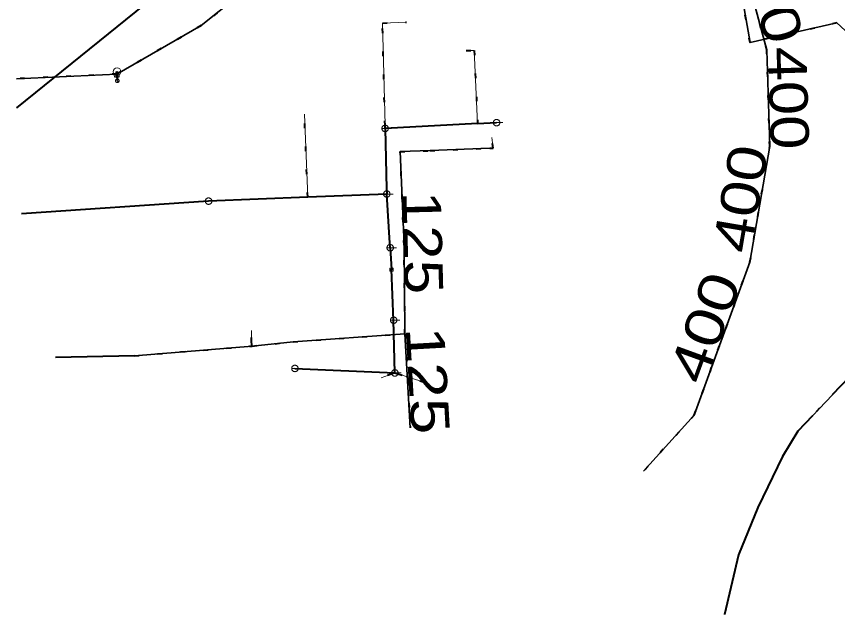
# Model space of a CAD drawing. Extents: x -968691 to -140888, y -1376050 to -879856.
# Drawn here: x -648096 to -647839.9, y -1059378.8 to -1059192.1 of the extents above; entities that cross this region are included whole.
import ezdxf
from ezdxf.enums import TextEntityAlignment as Align

# ---------------------------------------------------------------- set-up
doc = ezdxf.new("R2010")
doc.units = 0
doc.header["$LTSCALE"] = 4.8
doc.header["$PDMODE"] = 32
doc.header["$PDSIZE"] = 2.4
for name, pattern in [('DASH_DOUBLE_DOT', [9.2, 5, -1.2, 0.3, -1.2, 0.3, -1.2]), ('DOTTED', [1.5, 0.3, -1.2]), ('LONG_DASHED', [7.5, 6, -1.5])]:
    doc.linetypes.add(name, pattern=pattern)
doc.layers.add('1', color=7, linetype='Continuous', lineweight=13)

msp = doc.modelspace()

# ---------------------------------------------------------------- linework, layer by layer
at = {"layer": '1', "linetype": 'DOTTED', "lineweight": 40}
for p, q in [((-647861.94, -1059202.67), (-647872.07, -1059164.99)), ((-647861.03, -1059232.57), (-647861.94, -1059202.67)), ((-648064.708, -1059210.087), (-648096.041, -1059211.538)), ((-648064.708, -1059210.087), (-648064.769, -1059210.614)), ((-648064.769, -1059210.614), (-648064.568, -1059212.171)), ((-648005.171, -1059248.515), (-648006.216, -1059222.562)), ((-647981.033, -1059227.048), (-647981.057, -1059226.076)), ((-647947.353, -1059233.222), (-647947.698, -1059229.929)), ((-647867.21, -1059268.79), (-647861.03, -1059232.57)), ((-647884.58, -1059316.54), (-647867.21, -1059268.79)), ((-647974.834, -1059291.188), (-647973.19, -1059320.48)), ((-648059.23, -1059298), (-648022.517, -1059294.974)), ((-647884.58, -1059316.54), (-647900.42, -1059334))]:
    msp.add_line(p, q, dxfattribs=at)
at = {"layer": '1', "lineweight": 35}
for p, q in [((-647861.94, -1059202.67), (-647872.07, -1059164.99)), ((-648056.094, -1059188.331), (-648096.013, -1059220.63)), ((-647861.03, -1059232.57), (-647861.94, -1059202.67)), ((-648064.708, -1059210.087), (-648096.041, -1059211.538)), ((-647952.158, -1059225.555), (-647981.033, -1059227.048)), ((-647952.158, -1059225.555), (-647946.25, -1059225.25)), ((-647867.21, -1059268.79), (-647861.03, -1059232.57)), ((-648005.171, -1059248.515), (-648036.09, -1059249.75)), ((-648036.09, -1059249.75), (-648094.414, -1059253.722)), ((-647979.45, -1059264.3), (-647979.04, -1059271.13)), ((-647884.58, -1059316.54), (-647867.21, -1059268.79)), ((-647978.37, -1059286.92), (-647979.04, -1059271.13)), ((-647977.99, -1059303.36), (-647978.37, -1059286.92)), ((-647974.834, -1059291.188), (-647973.19, -1059320.48)), ((-648059.23, -1059298), (-648022.517, -1059294.974)), ((-648059.23, -1059298), (-648083.88, -1059298.54)), ((-648009.17, -1059301.96), (-647977.99, -1059303.36)), ((-647884.58, -1059316.54), (-647900.42, -1059334))]:
    msp.add_line(p, q, dxfattribs=at)
at = {"layer": '1', "lineweight": 40}
for p, q in [((-648056.094, -1059188.331), (-648096.013, -1059220.63)), ((-647952.158, -1059225.555), (-647981.033, -1059227.048)), ((-647952.158, -1059225.555), (-647946.25, -1059225.25)), ((-648005.171, -1059248.515), (-648036.09, -1059249.75)), ((-648036.09, -1059249.75), (-648094.414, -1059253.722)), ((-647979.45, -1059264.3), (-647979.04, -1059271.13)), ((-647978.37, -1059286.92), (-647979.04, -1059271.13)), ((-647977.99, -1059303.36), (-647978.37, -1059286.92)), ((-648009.17, -1059301.96), (-647977.99, -1059303.36))]:
    msp.add_line(p, q, dxfattribs=at)
at = {"layer": '1'}
for p, q in [((-648064.708, -1059210.087), (-648064.769, -1059210.614)), ((-648064.638, -1059209.346), (-648064.736, -1059209.346)), ((-648064.736, -1059211.124), (-648064.736, -1059209.346)), ((-648064.589, -1059209.569), (-648064.589, -1059210.01)), ((-648065.127, -1059211.102), (-648064.009, -1059211.102)), ((-648064.173, -1059212.567), (-648064.963, -1059211.776)), ((-648064.769, -1059210.614), (-648064.568, -1059212.171)), ((-648064.568, -1059211.613), (-648064.568, -1059211.102)), ((-648005.171, -1059248.515), (-648006.216, -1059222.562)), ((-647947.258, -1059225.25), (-647944.281, -1059225.25)), ((-647982.041, -1059227.048), (-647979.064, -1059227.048)), ((-647981.033, -1059227.048), (-647981.057, -1059226.076)), ((-647947.353, -1059233.222), (-647947.698, -1059229.929)), ((-647981.528, -1059247.53), (-647978.551, -1059247.53)), ((-648037.098, -1059249.75), (-648034.121, -1059249.75)), ((-647980.458, -1059264.3), (-647977.481, -1059264.3)), ((-647979.54, -1059271.13), (-647978.54, -1059271.13)), ((-647979.378, -1059286.92), (-647976.401, -1059286.92)), ((-648010.178, -1059301.96), (-648007.201, -1059301.96)), ((-647978.998, -1059303.36), (-647976.021, -1059303.36))]:
    msp.add_line(p, q, dxfattribs=at)
at = {"layer": '1', "linetype": 'LONG_DASHED', "lineweight": 40}
msp.add_line((-648059.23, -1059298), (-648083.88, -1059298.54), dxfattribs=at)
at = {"layer": '1', "linetype": 'DOTTED', "lineweight": 40}
for points in [[(-647831.099, -1059202.397), (-647840.069, -1059194.127), (-647867.192, -1059200.266), (-647876.082, -1059149.482), (-647878.022, -1059147.34), (-647916.85, -1059098.69)], [(-647933.16, -1059110.3), (-647982.806, -1059150.542), (-648038.371, -1059194.95), (-648064.708, -1059210.087)], [(-647981.057, -1059226.076), (-647981.859, -1059194.186), (-647974.377, -1059193.89)], [(-647955.7, -1059202.759), (-647953.238, -1059202.766), (-647952.158, -1059225.555)], [(-647974.834, -1059291.188), (-647975.11, -1059263.48), (-647976.31, -1059234.302), (-647967.01, -1059233.97), (-647948.33, -1059233.23), (-647947.353, -1059233.222)], [(-648022.517, -1059294.974), (-648022.68, -1059293.75), (-648022.71, -1059290.11)], [(-648022.517, -1059294.974), (-648009.71, -1059293.64), (-647974.834, -1059291.188)], [(-647977.99, -1059303.36), (-647978.879, -1059303.675), (-647982.251, -1059304.869)], [(-647977.99, -1059303.36), (-647977.033, -1059303.66), (-647967.251, -1059306.729)]]:
    msp.add_lwpolyline(points, dxfattribs=at)
at = {"layer": '1', "lineweight": 35}
for points in [[(-647831.099, -1059202.397), (-647840.069, -1059194.127), (-647867.192, -1059200.266), (-647876.082, -1059149.482), (-647878.022, -1059147.34), (-647916.85, -1059098.69)], [(-647933.16, -1059110.3), (-647982.806, -1059150.542), (-648038.371, -1059194.95), (-648064.708, -1059210.087)], [(-647981.033, -1059227.048), (-647980.56, -1059245.935), (-647980.52, -1059247.53), (-648005.171, -1059248.515)], [(-647974.834, -1059291.188), (-647975.11, -1059263.48), (-647976.31, -1059234.302), (-647967.01, -1059233.97), (-647948.33, -1059233.23), (-647947.353, -1059233.222)], [(-647979.45, -1059264.3), (-647979.544, -1059262.821), (-647980.52, -1059247.53)], [(-647790.53, -1059264.42), (-647798.147, -1059269.982), (-647808.729, -1059279.085), (-647824.987, -1059292.812), (-647847.758, -1059316.763), (-647852.291, -1059321.546), (-647857.02, -1059329.468), (-647864.807, -1059345.333), (-647870.759, -1059360.132), (-647875.166, -1059378.78)], [(-648022.517, -1059294.974), (-648009.71, -1059293.64), (-647974.834, -1059291.188)]]:
    msp.add_lwpolyline(points, dxfattribs=at)
at = {"layer": '1'}
for points in [[(-647981.057, -1059226.076), (-647981.859, -1059194.186), (-647974.377, -1059193.89)], [(-647955.7, -1059202.759), (-647953.238, -1059202.766), (-647952.158, -1059225.555)], [(-648022.517, -1059294.974), (-648022.68, -1059293.75), (-648022.71, -1059290.11)], [(-647977.99, -1059303.36), (-647978.879, -1059303.675), (-647982.251, -1059304.869)], [(-647977.99, -1059303.36), (-647977.033, -1059303.66), (-647967.251, -1059306.729)]]:
    msp.add_lwpolyline(points, dxfattribs=at)
for points in [[(-648064.042, -1059210.218), (-648063.998, -1059210.916), (-648065.54, -1059210.312), (-648065.496, -1059211.01)], [(-648065.037, -1059210.235), (-648064.435, -1059210.235), (-648064.435, -1059209.346), (-648065.037, -1059209.346)], [(-648064.659, -1059210.116), (-648064.512, -1059210.116), (-648064.512, -1059209.45), (-648064.659, -1059209.45)], [(-648064.009, -1059212.172), (-648064.018, -1059212.075), (-648064.043, -1059211.981), (-648064.084, -1059211.893), (-648064.14, -1059211.813), (-648064.209, -1059211.744), (-648064.289, -1059211.688), (-648064.377, -1059211.647), (-648064.471, -1059211.622), (-648064.568, -1059211.613), (-648064.665, -1059211.622), (-648064.759, -1059211.647), (-648064.847, -1059211.688), (-648064.927, -1059211.744), (-648064.996, -1059211.813), (-648065.052, -1059211.893), (-648065.093, -1059211.981), (-648065.118, -1059212.075), (-648065.127, -1059212.172), (-648065.118, -1059212.269), (-648065.093, -1059212.363), (-648065.052, -1059212.451), (-648064.996, -1059212.531), (-648064.927, -1059212.6), (-648064.847, -1059212.656), (-648064.759, -1059212.697), (-648064.665, -1059212.722), (-648064.568, -1059212.73), (-648064.471, -1059212.722), (-648064.377, -1059212.697), (-648064.289, -1059212.656), (-648064.209, -1059212.6), (-648064.14, -1059212.531), (-648064.084, -1059212.451), (-648064.043, -1059212.363), (-648064.018, -1059212.269)], [(-647946.25, -1059224.242), (-647946.355, -1059224.248), (-647946.459, -1059224.264), (-647946.561, -1059224.291), (-647946.659, -1059224.329), (-647946.753, -1059224.377), (-647946.841, -1059224.434), (-647946.924, -1059224.501), (-647946.999, -1059224.576), (-647947.065, -1059224.658), (-647947.122, -1059224.745), (-647947.169, -1059224.84), (-647947.207, -1059224.939), (-647947.235, -1059225.04), (-647947.251, -1059225.145), (-647947.258, -1059225.25), (-647947.251, -1059225.355), (-647947.235, -1059225.46), (-647947.207, -1059225.562), (-647947.169, -1059225.66), (-647947.122, -1059225.753), (-647947.065, -1059225.843), (-647946.999, -1059225.925), (-647946.924, -1059225.999), (-647946.841, -1059226.065), (-647946.753, -1059226.123), (-647946.659, -1059226.171), (-647946.561, -1059226.209), (-647946.459, -1059226.236), (-647946.355, -1059226.252), (-647946.25, -1059226.258), (-647946.144, -1059226.252), (-647946.039, -1059226.236), (-647945.938, -1059226.209), (-647945.84, -1059226.171), (-647945.745, -1059226.123), (-647945.657, -1059226.065), (-647945.575, -1059225.999), (-647945.5, -1059225.925), (-647945.434, -1059225.843), (-647945.377, -1059225.753), (-647945.328, -1059225.66), (-647945.29, -1059225.562), (-647945.264, -1059225.46), (-647945.248, -1059225.355), (-647945.242, -1059225.25), (-647945.248, -1059225.145), (-647945.264, -1059225.04), (-647945.29, -1059224.939), (-647945.328, -1059224.84), (-647945.377, -1059224.745), (-647945.434, -1059224.658), (-647945.5, -1059224.576), (-647945.575, -1059224.501), (-647945.657, -1059224.434), (-647945.745, -1059224.377), (-647945.84, -1059224.329), (-647945.938, -1059224.291), (-647946.039, -1059224.264), (-647946.144, -1059224.248)], [(-647981.033, -1059226.04), (-647981.138, -1059226.046), (-647981.242, -1059226.062), (-647981.344, -1059226.089), (-647981.442, -1059226.127), (-647981.536, -1059226.175), (-647981.624, -1059226.232), (-647981.707, -1059226.299), (-647981.782, -1059226.374), (-647981.848, -1059226.456), (-647981.905, -1059226.543), (-647981.952, -1059226.638), (-647981.99, -1059226.737), (-647982.018, -1059226.838), (-647982.034, -1059226.943), (-647982.041, -1059227.048), (-647982.034, -1059227.153), (-647982.018, -1059227.258), (-647981.99, -1059227.36), (-647981.952, -1059227.458), (-647981.905, -1059227.551), (-647981.848, -1059227.641), (-647981.782, -1059227.723), (-647981.707, -1059227.797), (-647981.624, -1059227.863), (-647981.536, -1059227.921), (-647981.442, -1059227.969), (-647981.344, -1059228.007), (-647981.242, -1059228.034), (-647981.138, -1059228.05), (-647981.033, -1059228.056), (-647980.927, -1059228.05), (-647980.822, -1059228.034), (-647980.721, -1059228.007), (-647980.623, -1059227.969), (-647980.528, -1059227.921), (-647980.44, -1059227.863), (-647980.358, -1059227.797), (-647980.283, -1059227.723), (-647980.217, -1059227.641), (-647980.16, -1059227.551), (-647980.111, -1059227.458), (-647980.073, -1059227.36), (-647980.047, -1059227.258), (-647980.031, -1059227.153), (-647980.025, -1059227.048), (-647980.031, -1059226.943), (-647980.047, -1059226.838), (-647980.073, -1059226.737), (-647980.111, -1059226.638), (-647980.16, -1059226.543), (-647980.217, -1059226.456), (-647980.283, -1059226.374), (-647980.358, -1059226.299), (-647980.44, -1059226.232), (-647980.528, -1059226.175), (-647980.623, -1059226.127), (-647980.721, -1059226.089), (-647980.822, -1059226.062), (-647980.927, -1059226.046)], [(-648036.09, -1059248.742), (-648036.195, -1059248.748), (-648036.299, -1059248.764), (-648036.401, -1059248.791), (-648036.499, -1059248.829), (-648036.593, -1059248.877), (-648036.681, -1059248.934), (-648036.764, -1059249.001), (-648036.839, -1059249.076), (-648036.905, -1059249.158), (-648036.962, -1059249.245), (-648037.009, -1059249.34), (-648037.047, -1059249.439), (-648037.075, -1059249.54), (-648037.091, -1059249.645), (-648037.098, -1059249.75), (-648037.091, -1059249.855), (-648037.075, -1059249.96), (-648037.047, -1059250.062), (-648037.009, -1059250.16), (-648036.962, -1059250.253), (-648036.905, -1059250.343), (-648036.839, -1059250.425), (-648036.764, -1059250.499), (-648036.681, -1059250.565), (-648036.593, -1059250.623), (-648036.499, -1059250.671), (-648036.401, -1059250.709), (-648036.299, -1059250.736), (-648036.195, -1059250.752), (-648036.09, -1059250.758), (-648035.984, -1059250.752), (-648035.879, -1059250.736), (-648035.778, -1059250.709), (-648035.68, -1059250.671), (-648035.585, -1059250.623), (-648035.497, -1059250.565), (-648035.415, -1059250.499), (-648035.34, -1059250.425), (-648035.274, -1059250.343), (-648035.217, -1059250.253), (-648035.168, -1059250.16), (-648035.13, -1059250.062), (-648035.104, -1059249.96), (-648035.088, -1059249.855), (-648035.082, -1059249.75), (-648035.088, -1059249.645), (-648035.104, -1059249.54), (-648035.13, -1059249.439), (-648035.168, -1059249.34), (-648035.217, -1059249.245), (-648035.274, -1059249.158), (-648035.34, -1059249.076), (-648035.415, -1059249.001), (-648035.497, -1059248.934), (-648035.585, -1059248.877), (-648035.68, -1059248.829), (-648035.778, -1059248.791), (-648035.879, -1059248.764), (-648035.984, -1059248.748)], [(-647980.52, -1059246.522), (-647980.625, -1059246.528), (-647980.729, -1059246.544), (-647980.831, -1059246.571), (-647980.929, -1059246.609), (-647981.023, -1059246.657), (-647981.111, -1059246.714), (-647981.194, -1059246.781), (-647981.269, -1059246.856), (-647981.335, -1059246.938), (-647981.392, -1059247.025), (-647981.439, -1059247.12), (-647981.477, -1059247.219), (-647981.505, -1059247.32), (-647981.521, -1059247.425), (-647981.528, -1059247.53), (-647981.521, -1059247.635), (-647981.505, -1059247.74), (-647981.477, -1059247.842), (-647981.439, -1059247.94), (-647981.392, -1059248.033), (-647981.335, -1059248.123), (-647981.269, -1059248.205), (-647981.194, -1059248.279), (-647981.111, -1059248.345), (-647981.023, -1059248.403), (-647980.929, -1059248.451), (-647980.831, -1059248.489), (-647980.729, -1059248.516), (-647980.625, -1059248.532), (-647980.52, -1059248.538), (-647980.414, -1059248.532), (-647980.309, -1059248.516), (-647980.208, -1059248.489), (-647980.11, -1059248.451), (-647980.015, -1059248.403), (-647979.927, -1059248.345), (-647979.845, -1059248.279), (-647979.77, -1059248.205), (-647979.704, -1059248.123), (-647979.647, -1059248.033), (-647979.598, -1059247.94), (-647979.56, -1059247.842), (-647979.534, -1059247.74), (-647979.518, -1059247.635), (-647979.512, -1059247.53), (-647979.518, -1059247.425), (-647979.534, -1059247.32), (-647979.56, -1059247.219), (-647979.598, -1059247.12), (-647979.647, -1059247.025), (-647979.704, -1059246.938), (-647979.77, -1059246.856), (-647979.845, -1059246.781), (-647979.927, -1059246.714), (-647980.015, -1059246.657), (-647980.11, -1059246.609), (-647980.208, -1059246.571), (-647980.309, -1059246.544), (-647980.414, -1059246.528)], [(-647979.45, -1059263.292), (-647979.555, -1059263.298), (-647979.659, -1059263.314), (-647979.761, -1059263.341), (-647979.859, -1059263.379), (-647979.953, -1059263.427), (-647980.041, -1059263.484), (-647980.124, -1059263.551), (-647980.199, -1059263.626), (-647980.265, -1059263.708), (-647980.322, -1059263.795), (-647980.369, -1059263.89), (-647980.407, -1059263.989), (-647980.435, -1059264.09), (-647980.451, -1059264.195), (-647980.458, -1059264.3), (-647980.451, -1059264.405), (-647980.435, -1059264.51), (-647980.407, -1059264.612), (-647980.369, -1059264.71), (-647980.322, -1059264.803), (-647980.265, -1059264.893), (-647980.199, -1059264.975), (-647980.124, -1059265.049), (-647980.041, -1059265.115), (-647979.953, -1059265.173), (-647979.859, -1059265.221), (-647979.761, -1059265.259), (-647979.659, -1059265.286), (-647979.555, -1059265.302), (-647979.45, -1059265.308), (-647979.344, -1059265.302), (-647979.239, -1059265.286), (-647979.138, -1059265.259), (-647979.04, -1059265.221), (-647978.945, -1059265.173), (-647978.857, -1059265.115), (-647978.775, -1059265.049), (-647978.7, -1059264.975), (-647978.634, -1059264.893), (-647978.577, -1059264.803), (-647978.528, -1059264.71), (-647978.49, -1059264.612), (-647978.464, -1059264.51), (-647978.448, -1059264.405), (-647978.442, -1059264.3), (-647978.448, -1059264.195), (-647978.464, -1059264.09), (-647978.49, -1059263.989), (-647978.528, -1059263.89), (-647978.577, -1059263.795), (-647978.634, -1059263.708), (-647978.7, -1059263.626), (-647978.775, -1059263.551), (-647978.857, -1059263.484), (-647978.945, -1059263.427), (-647979.04, -1059263.379), (-647979.138, -1059263.341), (-647979.239, -1059263.314), (-647979.344, -1059263.298)], [(-647979.54, -1059271.63), (-647978.54, -1059271.63), (-647978.54, -1059270.63), (-647979.54, -1059270.63)], [(-647978.37, -1059285.912), (-647978.475, -1059285.918), (-647978.579, -1059285.934), (-647978.681, -1059285.961), (-647978.779, -1059285.999), (-647978.873, -1059286.047), (-647978.961, -1059286.104), (-647979.044, -1059286.171), (-647979.119, -1059286.246), (-647979.185, -1059286.328), (-647979.242, -1059286.415), (-647979.289, -1059286.51), (-647979.327, -1059286.609), (-647979.355, -1059286.71), (-647979.371, -1059286.815), (-647979.378, -1059286.92), (-647979.371, -1059287.025), (-647979.355, -1059287.13), (-647979.327, -1059287.232), (-647979.289, -1059287.33), (-647979.242, -1059287.423), (-647979.185, -1059287.513), (-647979.119, -1059287.595), (-647979.044, -1059287.669), (-647978.961, -1059287.735), (-647978.873, -1059287.793), (-647978.779, -1059287.841), (-647978.681, -1059287.879), (-647978.579, -1059287.906), (-647978.475, -1059287.922), (-647978.37, -1059287.928), (-647978.264, -1059287.922), (-647978.159, -1059287.906), (-647978.058, -1059287.879), (-647977.96, -1059287.841), (-647977.865, -1059287.793), (-647977.777, -1059287.735), (-647977.695, -1059287.669), (-647977.62, -1059287.595), (-647977.554, -1059287.513), (-647977.497, -1059287.423), (-647977.448, -1059287.33), (-647977.41, -1059287.232), (-647977.384, -1059287.13), (-647977.368, -1059287.025), (-647977.362, -1059286.92), (-647977.368, -1059286.815), (-647977.384, -1059286.71), (-647977.41, -1059286.609), (-647977.448, -1059286.51), (-647977.497, -1059286.415), (-647977.554, -1059286.328), (-647977.62, -1059286.246), (-647977.695, -1059286.171), (-647977.777, -1059286.104), (-647977.865, -1059286.047), (-647977.96, -1059285.999), (-647978.058, -1059285.961), (-647978.159, -1059285.934), (-647978.264, -1059285.918)], [(-648009.17, -1059300.952), (-648009.275, -1059300.958), (-648009.379, -1059300.974), (-648009.481, -1059301.001), (-648009.579, -1059301.039), (-648009.673, -1059301.087), (-648009.761, -1059301.144), (-648009.844, -1059301.211), (-648009.919, -1059301.286), (-648009.985, -1059301.368), (-648010.042, -1059301.455), (-648010.089, -1059301.55), (-648010.127, -1059301.649), (-648010.155, -1059301.75), (-648010.171, -1059301.855), (-648010.178, -1059301.96), (-648010.171, -1059302.065), (-648010.155, -1059302.17), (-648010.127, -1059302.272), (-648010.089, -1059302.37), (-648010.042, -1059302.463), (-648009.985, -1059302.553), (-648009.919, -1059302.635), (-648009.844, -1059302.709), (-648009.761, -1059302.775), (-648009.673, -1059302.833), (-648009.579, -1059302.881), (-648009.481, -1059302.919), (-648009.379, -1059302.946), (-648009.275, -1059302.962), (-648009.17, -1059302.968), (-648009.064, -1059302.962), (-648008.959, -1059302.946), (-648008.858, -1059302.919), (-648008.76, -1059302.881), (-648008.665, -1059302.833), (-648008.577, -1059302.775), (-648008.495, -1059302.709), (-648008.42, -1059302.635), (-648008.354, -1059302.553), (-648008.297, -1059302.463), (-648008.248, -1059302.37), (-648008.21, -1059302.272), (-648008.184, -1059302.17), (-648008.168, -1059302.065), (-648008.162, -1059301.96), (-648008.168, -1059301.855), (-648008.184, -1059301.75), (-648008.21, -1059301.649), (-648008.248, -1059301.55), (-648008.297, -1059301.455), (-648008.354, -1059301.368), (-648008.42, -1059301.286), (-648008.495, -1059301.211), (-648008.577, -1059301.144), (-648008.665, -1059301.087), (-648008.76, -1059301.039), (-648008.858, -1059301.001), (-648008.959, -1059300.974), (-648009.064, -1059300.958)], [(-647977.99, -1059302.352), (-647978.095, -1059302.358), (-647978.199, -1059302.374), (-647978.301, -1059302.401), (-647978.399, -1059302.439), (-647978.493, -1059302.487), (-647978.581, -1059302.544), (-647978.664, -1059302.611), (-647978.739, -1059302.686), (-647978.805, -1059302.768), (-647978.862, -1059302.855), (-647978.909, -1059302.95), (-647978.947, -1059303.049), (-647978.975, -1059303.15), (-647978.991, -1059303.255), (-647978.998, -1059303.36), (-647978.991, -1059303.465), (-647978.975, -1059303.57), (-647978.947, -1059303.672), (-647978.909, -1059303.77), (-647978.862, -1059303.863), (-647978.805, -1059303.953), (-647978.739, -1059304.035), (-647978.664, -1059304.109), (-647978.581, -1059304.175), (-647978.493, -1059304.233), (-647978.399, -1059304.281), (-647978.301, -1059304.319), (-647978.199, -1059304.346), (-647978.095, -1059304.362), (-647977.99, -1059304.368), (-647977.884, -1059304.362), (-647977.779, -1059304.346), (-647977.678, -1059304.319), (-647977.58, -1059304.281), (-647977.485, -1059304.233), (-647977.397, -1059304.175), (-647977.315, -1059304.109), (-647977.24, -1059304.035), (-647977.174, -1059303.953), (-647977.117, -1059303.863), (-647977.068, -1059303.77), (-647977.03, -1059303.672), (-647977.004, -1059303.57), (-647976.988, -1059303.465), (-647976.982, -1059303.36), (-647976.988, -1059303.255), (-647977.004, -1059303.15), (-647977.03, -1059303.049), (-647977.068, -1059302.95), (-647977.117, -1059302.855), (-647977.174, -1059302.768), (-647977.24, -1059302.686), (-647977.315, -1059302.611), (-647977.397, -1059302.544), (-647977.485, -1059302.487), (-647977.58, -1059302.439), (-647977.678, -1059302.401), (-647977.779, -1059302.374), (-647977.884, -1059302.358)]]:
    msp.add_lwpolyline(points, close=True, dxfattribs=at)
at = {"layer": '1', "lineweight": 40}
for points in [[(-647981.033, -1059227.048), (-647980.56, -1059245.935), (-647980.52, -1059247.53), (-648005.171, -1059248.515)], [(-647979.45, -1059264.3), (-647979.544, -1059262.821), (-647980.52, -1059247.53)]]:
    msp.add_lwpolyline(points, dxfattribs=at)
at = {"layer": '1', "linetype": 'DASH_DOUBLE_DOT', "lineweight": 40}
msp.add_lwpolyline([(-647790.53, -1059264.42), (-647798.147, -1059269.982), (-647808.729, -1059279.085), (-647824.987, -1059292.812), (-647847.758, -1059316.763), (-647852.291, -1059321.546), (-647857.02, -1059329.468), (-647864.807, -1059345.333), (-647870.759, -1059360.132), (-647875.166, -1059378.78)], dxfattribs=at)
at = {"layer": '1'}
msp.add_circle((-648064.769, -1059210.614), 0.132, dxfattribs=at)
msp.add_point((-648064.638, -1059209.346), dxfattribs=at)

# ---------------------------------------------------------------- texts
for s, rotation, width, p in [('BET 1600', 309.134, 1.2, (-647832.326, -1059174.895)), ('400', 285.048, 1.3, (-647866.44, -1059184.774)), ('400', 271.743, 1.2, (-647861.181, -1059217.73)), ('400', 80.317, 1.25, (-647864.303, -1059249.967)), ('125', 271.486, 1.2, (-647975.269, -1059262.838)), ('400', 70.01, 1.3, (-647875.687, -1059291.216)), ('125', 273.212, 1.25, (-647973.7, -1059306.038))]:
    msp.add_text(s, height=12, rotation=rotation, dxfattribs=dict(at, width=width)).set_placement(p, align=Align.CENTER)

doc.saveas('drawing.dxf')
